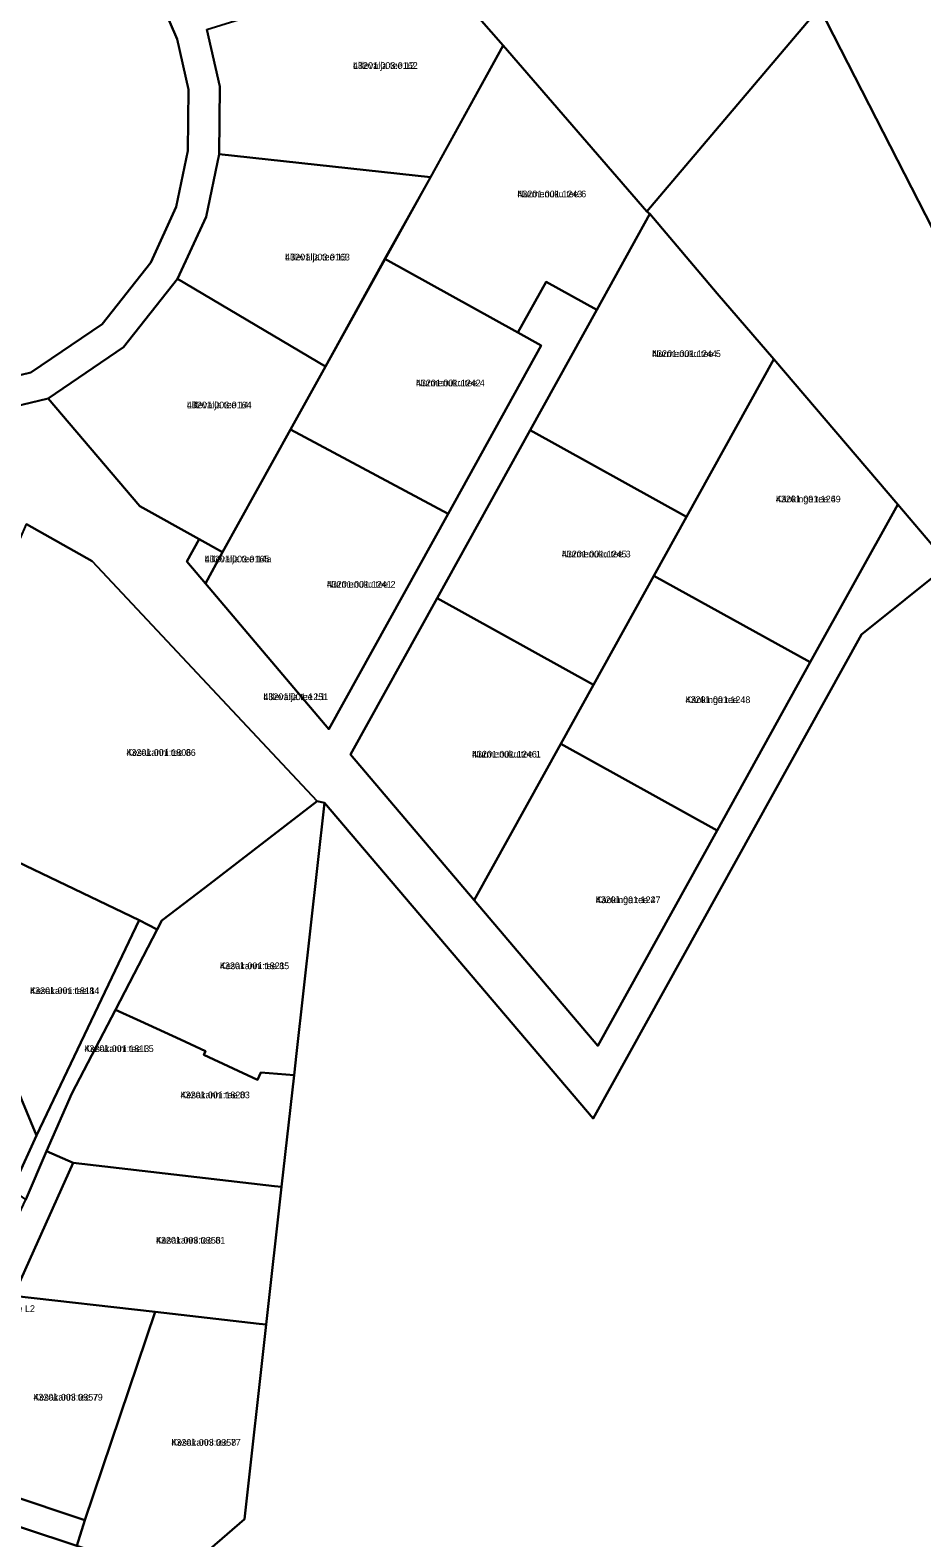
# Model space of a CAD drawing. Extents: x 661852 to 683758, y 6469495 to 6482657.
# Drawn here: x 663582 to 663781.6, y 6470786.6 to 6471124 of the extents above; entities that cross this region are included whole.
import ezdxf

# ---------------------------------------------------------------- set-up
doc = ezdxf.new("R2010")
doc.units = 0
for name, color, linetype in [('L_AADRESS', 7, 'Continuous'), ('PIIR', 7, 'Continuous'), ('TUNNUS', 7, 'Continuous')]:
    doc.layers.add(name, color=color, linetype=linetype)

msp = doc.modelspace()

# ---------------------------------------------------------------- linework, layer by layer
at = {"layer": 'PIIR'}
for points in [[(664046.81, 6471419.45), (664072.52, 6471363.28), (664035.02, 6471324.48), (663895.37, 6471178.77), (663893.87, 6471122.66), (663888.55, 6471044.81), (663799.89, 6471048.55), (663758.66, 6471128.97), (663720.04, 6471083.39), (663687.85, 6471120.5), (663671.24, 6471139.52), (663654.71, 6471158.71), (663687.16, 6471222.56), (663709.19, 6471265.46), (663733.78, 6471313.73), (663787.07, 6471363.65), (663788.62, 6471365.1), (663851.31, 6471427.4)], [(663621.58, 6471124.08), (663624.43, 6471111.39), (663624.29, 6471096.18), (663621.37, 6471082.21), (663615.01, 6471068.31), (663602.92, 6471053.03), (663586.06, 6471041.57), (663556.77, 6471034.51)], [(663556.77, 6471034.51), (663586.06, 6471041.57), (663606.55, 6471017.45), (663619.85, 6471010.08), (663617.07, 6471005.06), (663621.22, 6471000.17), (663648.88, 6470967.58), (663675.58, 6471015.76), (663696.42, 6471053.38), (663691.17, 6471056.28), (663697.47, 6471067.65), (663708.84, 6471061.35), (663693.95, 6471034.48), (663673.11, 6470996.86), (663653.73, 6470961.87), (663681.4, 6470929.29), (663709.08, 6470896.71), (663735.78, 6470944.89), (663756.62, 6470982.51), (663776.2, 6471017.83), (663787.66, 6471004.42), (663768.09, 6470988.77), (663708.04, 6470880.45), (663647.88, 6470951.1), (663646.23, 6470951.41), (663595.89, 6471005.17), (663581.2, 6471013.42)], [(663614.45, 6470777.36), (663629.96, 6470790.75), (663634.82, 6470834.35), (663638.27, 6470865.13), (663641.07, 6470890.16), (663641.61, 6470894.99), (663647.88, 6470951.1), (663708.04, 6470880.45), (663768.09, 6470988.77), (663787.66, 6471004.42), (663878.91, 6470897.46), (663881.76, 6470894.19), (663883.28, 6470892.46), (663932.2, 6470835.62), (663933.69, 6470833.88), (663914.13, 6470819.15), (663906.77, 6470813.73), (663889.86, 6470800.23), (663876.73, 6470789.67), (663865.8, 6470781.3)], [(663530.33, 6470764.71), (663540.88, 6470796.06), (663548.1, 6470817.83), (663548.76, 6470817.59), (663554.28, 6470820.53), (663556.8, 6470823.2), (663568.84, 6470836.28), (663581.03, 6470862.33), (663585.7, 6470873.09), (663591.6, 6470870.53), (663578.28, 6470840.78), (663576.95, 6470837.93), (663558.35, 6470816.86), (663555.55, 6470808.71), (663558.77, 6470802.43), (663594.23, 6470790.52), (663592.44, 6470784.79), (663556.82, 6470796.63), (663550.5, 6470793.54), (663542.27, 6470768.88)]]:
    msp.add_lwpolyline(points, dxfattribs=at)
for points in [[(663502.42, 6471137.71), (663521.22, 6471155.15), (663541.91, 6471164.59), (663560.63, 6471165.41), (663572.84, 6471163.17), (663585.45, 6471157.96), (663599.54, 6471147.99), (663609.78, 6471133.99), (663614.89, 6471121.93), (663617.42, 6471110.65), (663617.3, 6471096.94), (663614.68, 6471084.41), (663609, 6471071.99), (663598.1, 6471058.21), (663582.13, 6471047.36), (663557.62, 6471041.46), (663539.61, 6471043.68), (663520.92, 6471051.57), (663507.35, 6471064.62), (663497.58, 6471080.34), (663493.71, 6471100.07), (663495.02, 6471116.78)], [(663502.42, 6471137.71), (663495.02, 6471116.78), (663493.71, 6471100.07), (663497.58, 6471080.34), (663507.35, 6471064.62), (663520.92, 6471051.57), (663539.61, 6471043.68), (663557.62, 6471041.46), (663582.13, 6471047.36), (663598.1, 6471058.21), (663609, 6471071.99), (663614.68, 6471084.41), (663617.3, 6471096.94), (663617.42, 6471110.65), (663614.89, 6471121.93), (663609.78, 6471133.99), (663599.54, 6471147.99), (663585.45, 6471157.96), (663572.84, 6471163.17), (663560.63, 6471165.41), (663541.91, 6471164.59), (663521.22, 6471155.15)], [(663621.58, 6471124.08), (663671.24, 6471139.52), (663687.85, 6471120.5), (663671.59, 6471091.09), (663624.29, 6471096.18), (663624.43, 6471111.39)], [(663776.2, 6471017.83), (663748.48, 6471050.31), (663735.75, 6471065.05), (663720.74, 6471082.83), (663720.04, 6471083.39), (663758.66, 6471128.97), (663799.89, 6471048.55), (663888.55, 6471044.81), (663878.91, 6470897.46), (663787.66, 6471004.42)], [(663671.58, 6471091.03), (663687.85, 6471120.5), (663720.04, 6471083.39), (663720.74, 6471082.83), (663708.84, 6471061.35), (663697.47, 6471067.65), (663691.17, 6471056.28), (663661.41, 6471072.78)], [(663624.29, 6471096.18), (663671.59, 6471091.09), (663648.09, 6471048.67), (663615.01, 6471068.31), (663621.37, 6471082.21)], [(663708.84, 6471061.35), (663720.74, 6471082.83), (663735.75, 6471065.05), (663748.48, 6471050.31), (663728.94, 6471015.09), (663693.95, 6471034.48)], [(663648.09, 6471048.67), (663661.41, 6471072.78), (663691.17, 6471056.28), (663696.42, 6471053.38), (663675.58, 6471015.76), (663640.3, 6471034.62)], [(663602.92, 6471053.03), (663615.01, 6471068.31), (663648.09, 6471048.67), (663640.3, 6471034.62), (663625.09, 6471007.17), (663619.85, 6471010.08), (663606.55, 6471017.45), (663586.06, 6471041.57)], [(663728.94, 6471015.09), (663748.48, 6471050.31), (663776.2, 6471017.83), (663756.62, 6470982.51), (663721.63, 6471001.89)], [(663625.09, 6471007.17), (663640.3, 6471034.62), (663675.58, 6471015.76), (663648.88, 6470967.58), (663621.22, 6471000.17)], [(663673.11, 6470996.86), (663693.95, 6471034.48), (663728.94, 6471015.09), (663721.63, 6471001.89), (663708.1, 6470977.48)], [(663606.42, 6470924.82), (663560.9, 6470946.61), (663574.28, 6470977.43), (663566.96, 6470980.61), (663581.2, 6471013.42), (663595.89, 6471005.17), (663646.23, 6470951.41), (663621.21, 6470932.15), (663611.47, 6470924.75), (663610.42, 6470922.73)], [(663619.85, 6471010.08), (663625.09, 6471007.17), (663621.22, 6471000.17), (663617.07, 6471005.06)], [(663708.1, 6470977.48), (663721.63, 6471001.89), (663756.62, 6470982.51), (663735.78, 6470944.89), (663700.79, 6470964.28)], [(663653.73, 6470961.87), (663673.11, 6470996.86), (663708.1, 6470977.48), (663700.79, 6470964.28), (663681.4, 6470929.29)], [(663556.07, 6470969.36), (663561.87, 6470982.75), (663566.96, 6470980.61), (663574.28, 6470977.43), (663560.9, 6470946.61), (663557.56, 6470938.94), (663583.41, 6470876.63), (663578.86, 6470866.61), (663555.49, 6470923.08), (663548.92, 6470939), (663558.84, 6470961.94)], [(663681.4, 6470929.29), (663700.79, 6470964.28), (663735.78, 6470944.89), (663709.08, 6470896.71)], [(663601.08, 6470904.78), (663610.42, 6470922.73), (663611.47, 6470924.75), (663621.21, 6470932.15), (663646.23, 6470951.41), (663647.88, 6470951.1), (663641.61, 6470894.99), (663641.07, 6470890.16), (663633.65, 6470890.71), (663632.91, 6470889.12), (663620.9, 6470894.7), (663621.28, 6470895.52), (663615.65, 6470898.08), (663606.7, 6470902.2)], [(663606.42, 6470924.82), (663583.41, 6470876.63), (663557.56, 6470938.94), (663560.9, 6470946.61)], [(663581.03, 6470862.33), (663579.55, 6470863.33), (663577.91, 6470864.46), (663578.86, 6470866.61), (663583.41, 6470876.63), (663606.42, 6470924.82), (663610.42, 6470922.73), (663601.08, 6470904.78), (663591.34, 6470886.06), (663585.7, 6470873.09)], [(663591.34, 6470886.06), (663601.08, 6470904.78), (663606.7, 6470902.2), (663615.65, 6470898.08), (663621.28, 6470895.52), (663620.9, 6470894.7), (663632.91, 6470889.12), (663633.65, 6470890.71), (663641.07, 6470890.16), (663638.27, 6470865.13), (663636.72, 6470865.31), (663591.6, 6470870.53), (663585.7, 6470873.09)], [(663591.6, 6470870.53), (663636.72, 6470865.31), (663638.27, 6470865.13), (663634.82, 6470834.35), (663633.3, 6470834.52), (663609.96, 6470837.19), (663578.28, 6470840.78)], [(663578.28, 6470840.78), (663609.96, 6470837.19), (663594.23, 6470790.52), (663558.77, 6470802.43), (663555.55, 6470808.71), (663558.35, 6470816.86), (663576.95, 6470837.93)], [(663609.96, 6470837.19), (663633.3, 6470834.52), (663634.82, 6470834.35), (663629.96, 6470790.75), (663614.45, 6470777.36), (663613.06, 6470777.81), (663592.44, 6470784.79), (663594.23, 6470790.52)], [(663550.5, 6470793.54), (663556.82, 6470796.63), (663592.44, 6470784.79), (663613.06, 6470777.81), (663614.45, 6470777.36), (663586.41, 6470754.05), (663585.05, 6470754.51), (663542.27, 6470768.88)]]:
    msp.add_lwpolyline(points, close=True, dxfattribs=at)

# ---------------------------------------------------------------- texts
at = {"layer": 'L_AADRESS'}
for s, p in [('Lillevälja tee 12', (663654.26, 6471115.3)), ('Nurmenuku tee 6', (663691.07, 6471086.56)), ('Lillevälja tee 13', (663639.07, 6471072.43)), ('Nurmenuku tee 5', (663721.21, 6471050.82)), ('Nurmenuku tee 4', (663668.36, 6471044.27)), ('Lillevälja tee 14', (663617.08, 6471039.35)), ('Käokinga tee 6', (663748.92, 6471018.29)), ('Lillevälja tee 14a', (663621.08, 6471004.87)), ('Nurmenuku tee 3', (663701.02, 6471005.98)), ('Nurmenuku tee 2', (663648.4, 6470999.22)), ('Lillevälja tee L1', (663634.21, 6470974.05)), ('Käokinga tee 4', (663728.7, 6470973.39)), ('Kesakanni tee 86', (663603.56, 6470961.58)), ('Nurmenuku tee 1', (663680.91, 6470961.2)), ('Käokinga tee 2', (663708.59, 6470928.62)), ('Kesakanni tee 85', (663624.48, 6470913.85)), ('Kesakanni tee 84', (663581.99, 6470908.28)), ('Kesakanni tee L5', (663594.16, 6470895.32)), ('Kesakanni tee 83', (663615.67, 6470884.96)), ('Kesakanni tee 81', (663610.17, 6470852.44)), ('Kesakanni tee L2', (663567.58, 6470837.15)), ('Kesakanni tee 79', (663582.75, 6470817.32)), ('Kesakanni tee 77', (663613.63, 6470807.2))]:
    msp.add_text(s, height=1.5, dxfattribs=at).set_placement(p)
at = {"layer": 'TUNNUS'}
for s, p in [('43201:003:0162', (663654.26, 6471115.3)), ('43201:001:1243', (663691.07, 6471086.56)), ('43201:003:0163', (663639.07, 6471072.43)), ('43201:001:1244', (663721.21, 6471050.82)), ('43201:001:1242', (663668.36, 6471044.27)), ('43201:003:0164', (663617.08, 6471039.35)), ('43201:001:1249', (663748.92, 6471018.29)), ('43201:003:0165', (663621.08, 6471004.87)), ('43201:001:1245', (663701.02, 6471005.98)), ('43201:001:1241', (663648.4, 6470999.22)), ('43201:001:1251', (663634.21, 6470974.05)), ('43201:001:1248', (663728.7, 6470973.39)), ('43201:001:1806', (663603.56, 6470961.58)), ('43201:001:1246', (663680.91, 6470961.2)), ('43201:001:1247', (663708.59, 6470928.62)), ('43201:001:1821', (663624.48, 6470913.85)), ('43201:001:1811', (663581.99, 6470908.28)), ('43201:001:1813', (663594.16, 6470895.32)), ('43201:001:1820', (663615.67, 6470884.96)), ('43201:003:0356', (663610.17, 6470852.44)), ('43201:003:0357', (663582.75, 6470817.32)), ('43201:003:0358', (663613.63, 6470807.2))]:
    msp.add_text(s, height=1.5, dxfattribs=at).set_placement(p)

doc.saveas('drawing.dxf')
